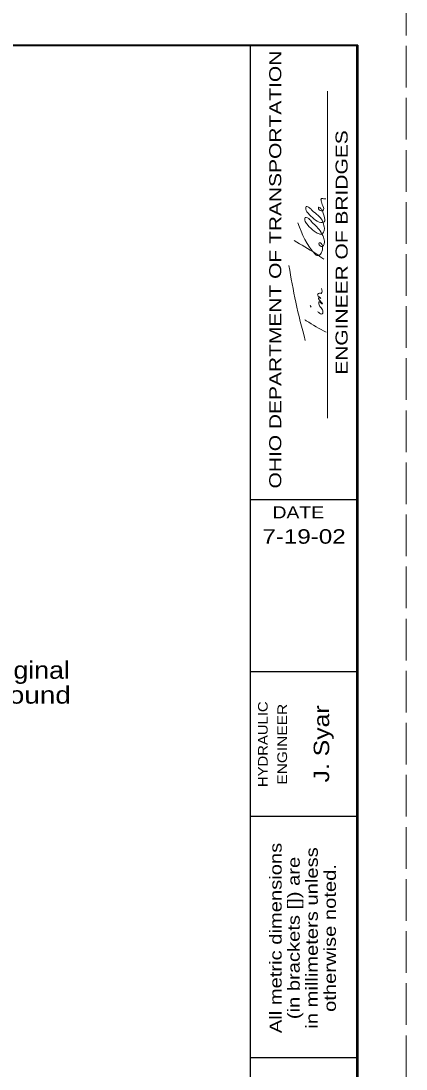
# Model space of a CAD drawing. Extents: x 750.7 to 784.7, y 834.8 to 878.8.
# Drawn here: x 780.66 to 784.65, y 845.67 to 856.53 of the extents above; entities that cross this region are included whole.
import ezdxf
from ezdxf.enums import TextEntityAlignment as Align

# ---------------------------------------------------------------- set-up
doc = ezdxf.new("R2010")
doc.units = 0
doc.header["$LTSCALE"] = 0.072
doc.linetypes.add('LONG_DASHED', pattern=[7.5, 6, -1.5])
doc.layers.add('1', color=7, linetype='Continuous', lineweight=13)

msp = doc.modelspace()

# ---------------------------------------------------------------- linework, layer by layer
at = {"layer": '1', "lineweight": 40}
for p, q in [((752.65083, 856.28433), (784.15083, 856.28433)), ((784.147, 856.28433), (784.147, 835.28433))]:
    msp.add_line(p, q, dxfattribs=at)
at = {"layer": '1'}
for p, q in [((782.07833, 856.28433), (783.07842, 856.28433)), ((783.83592, 852.41533), (783.83592, 855.80542)), ((783.66842, 853.56625), (783.65825, 853.5855))]:
    msp.add_line(p, q, dxfattribs=at)
at = {"layer": '1', "lineweight": 25}
for p, q in [((783.03717, 835.28433), (783.03717, 856.28433)), ((784.13717, 856.28433), (784.13717, 835.28433)), ((784.13717, 851.5685), (783.03717, 851.5685)), ((784.13717, 849.78433), (783.03717, 849.78433)), ((784.13717, 848.28433), (783.03717, 848.28433)), ((784.13717, 845.78433), (783.03717, 845.78433))]:
    msp.add_line(p, q, dxfattribs=at)
at = {"layer": '1', "linetype": 'LONG_DASHED'}
msp.add_lwpolyline([(750.65083, 834.78433), (784.65083, 834.78433), (784.65083, 856.78433), (750.65083, 856.78433)], close=True, dxfattribs=at)
at = {"layer": '1', "lineweight": 40}
msp.add_lwpolyline([(784.15083, 835.28433), (752.65083, 835.28433), (752.65083, 856.28433), (784.15083, 856.28433)], dxfattribs=at)
at = {"layer": '1'}
for points in [[(783.529, 854.44133), (783.71217, 854.113), (783.72733, 854.10242), (783.7375, 854.10242), (783.76942, 854.12608), (783.7845, 854.16025), (783.7795, 854.2115), (783.76258, 854.23333), (783.74908, 854.23333), (783.74733, 854.22033), (783.7575, 854.20517), (783.771, 854.19675), (783.78608, 854.19675), (783.80125, 854.21833), (783.80467, 854.23767), (783.79442, 854.293), (783.71217, 854.41342), (783.66667, 854.45808), (783.62975, 854.49267), (783.60458, 854.49483), (783.60633, 854.45625), (783.6315, 854.4175), (783.69875, 854.35517), (783.74083, 854.32975), (783.7745, 854.32525), (783.79783, 854.35125), (783.80467, 854.38542), (783.79958, 854.41117), (783.76942, 854.48433), (783.73917, 854.51633), (783.67858, 854.56975), (783.64992, 854.59558), (783.61642, 854.61083), (783.613, 854.58283), (783.62308, 854.557), (783.68025, 854.49708), (783.75092, 854.44983), (783.80292, 854.45217), (783.80125, 854.50983), (783.78942, 854.55275), (783.77608, 854.5785), (783.76592, 854.58925), (783.7425, 854.60425), (783.74425, 854.58717), (783.7795, 854.56567), (783.79442, 854.57642), (783.78133, 854.63008), (783.77275, 854.658), (783.76942, 854.67067), (783.76942, 854.6835), (783.76942, 854.69217), (783.79442, 854.69), (783.81983, 854.69)], [(783.49017, 854.25908), (783.71392, 854.12158), (783.79958, 854.06592)], [(783.60642, 853.22208), (783.50775, 853.61733), (783.4365, 853.99967)], [(783.7375, 853.521), (783.74575, 853.51033), (783.78292, 853.49742), (783.78767, 853.52983), (783.76258, 853.56625), (783.74733, 853.6025), (783.74733, 853.62175), (783.76258, 853.6155), (783.77275, 853.60467), (783.78292, 853.60033), (783.75925, 853.6325), (783.74733, 853.6475), (783.74425, 853.66483), (783.76767, 853.65825), (783.75925, 853.66692), (783.73408, 853.69475), (783.74425, 853.70992), (783.761, 853.71192), (783.76942, 853.70992), (783.7795, 853.73125), (783.77275, 853.75917)], [(783.82158, 853.3065), (783.61642, 853.4265), (783.60083, 853.43692)]]:
    msp.add_spline(points, degree=3, dxfattribs=at)

# ---------------------------------------------------------------- texts
for s, height, width, p in [('OHIO DEPARTMENT OF TRANSPORTATION', 0.125, 1.3, (783.35708, 853.9565)), ('ENGINEER OF BRIDGES', 0.125, 1.3, (784.04542, 854.13329)), ('HYDRAULIC', 0.1, 1.15, (783.21625, 849.03533)), ('ENGINEER', 0.1, 1.2, (783.41717, 849.03537)), ('J. Syar', 0.16, 1.2, (783.85358, 849.03837)), ('All metric dimensions', 0.125, 1.25, (783.361, 847.02633)), ('in millimeters unless', 0.125, 1.25, (783.736, 847.02637)), ('(in brackets []) are', 0.125, 1.25, (783.5485, 847.02633)), ('otherwise noted.', 0.125, 1.25, (783.9235, 847.02633))]:
    msp.add_text(s, height=height, rotation=90, dxfattribs=dict(at, width=width)).set_placement(p, align=Align.CENTER)
for s, height, width, p in [('DATE', 0.125, 1.2, (783.53387, 851.377)), ('7-19-02', 0.15, 1.25, (783.59321, 851.11433))]:
    msp.add_text(s, height=height, dxfattribs=dict(at, width=width)).set_placement(p, align=Align.CENTER)
for s, width, p in [('Original', 1.15, (780.21158, 849.71408)), ('Ground', 1.2, (780.21158, 849.45608))]:
    msp.add_text(s, height=0.18, dxfattribs=dict(at, width=width)).set_placement(p)

doc.saveas('drawing.dxf')
